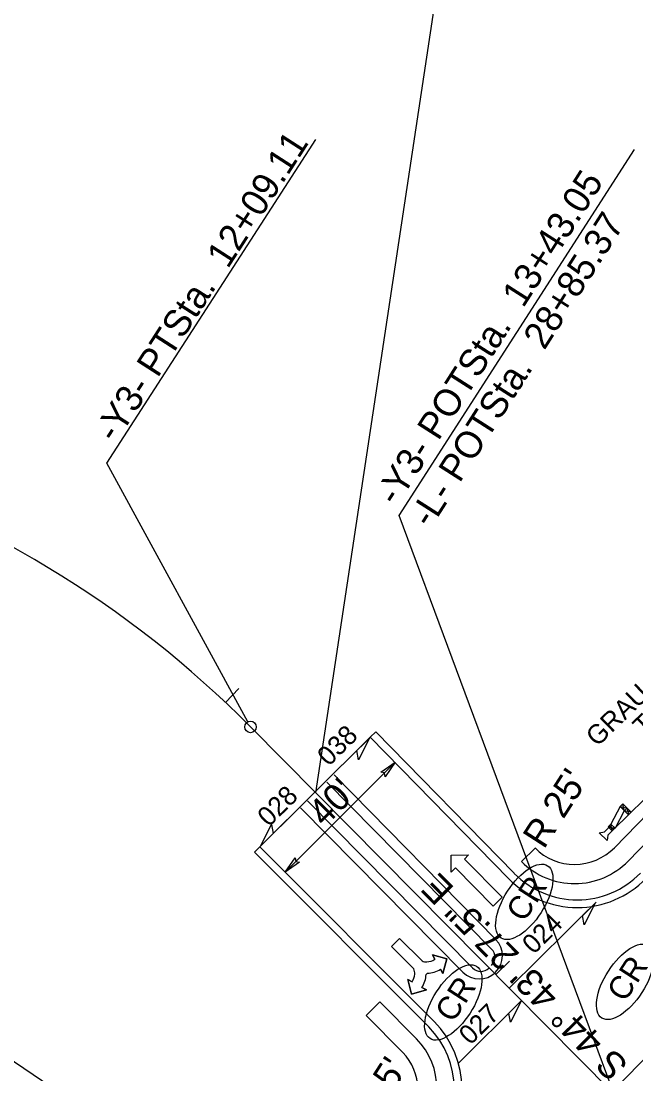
# Model space of a CAD drawing. Extents: x 1974386 to 1979988, y 776712 to 784860.
# Drawn here: x 1976659.3 to 1976819.6, y 779962.3 to 780236.8 of the extents above; entities that cross this region are included whole.
import ezdxf

# ---------------------------------------------------------------- set-up
doc = ezdxf.new("R2010")
doc.units = 0
for name, color, linetype in [('Prop Conc 2ft 6in Curb and Gutter', 7, 'Continuous'), ('Prop Conc 4in Sidewalk', 7, 'Continuous'), ('Prop Dimension', 7, 'Continuous'), ('Prop Dimension Text', 7, 'Continuous'), ('Prop EOT', 7, 'Continuous'), ('Prop Guardrail Anchor Unit CELL', 7, 'Continuous'), ('Prop Horizontal Alignment', 7, 'Continuous'), ('Prop Horizontal Alignment Direction Label', 7, 'Continuous'), ('Prop Horizontal Alignment Station Label', 7, 'Continuous'), ('Prop Horizontal Alignment Tick Small', 7, 'Continuous'), ('Prop Lane Arrow CELL', 7, 'Continuous'), ('Prop Superelevation  Arrow CELL', 7, 'Continuous'), ('Prop Superelevation Label', 7, 'Continuous'), ('Prop Terminator CELL', 7, 'Continuous'), ('Prop WCC CELL', 7, 'Continuous'), ('Sheet Layout Plan Border', 7, 'Continuous')]:
    doc.layers.add(name, color=color, linetype=linetype)

msp = doc.modelspace()

# ---------------------------------------------------------------- linework, layer by layer
at = {"layer": 'Prop Conc 2ft 6in Curb and Gutter'}
for p, q in [((1976751.75, 780051.46), (1976750.32, 780050.06)), ((1976751.75, 780051.46), (1976787.85, 780014.59)), ((1976738.98, 780038.4), (1976781.96, 779994.82)), ((1976733.99, 780033.46), (1976776.99, 779989.92)), ((1976720.09, 780020.1), (1976721.5, 780021.52)), ((1976720.09, 780020.1), (1976765.55, 779974.59))]:
    msp.add_line(p, q, dxfattribs=at)
for centre, radius, start, end in [((1976804.29, 780030.68), 23, 224.3953, 315.7395), ((1976779.82, 779992.71), 3, 314.6251, 44.6061), ((1976779.13, 779992.03), 3, 224.645, 314.6251), ((1976749.21, 779958.4), 23, 315.7395, 44.7138)]:
    msp.add_arc(centre, radius, start, end, dxfattribs=at)
at = {"layer": 'Prop Conc 4in Sidewalk'}
for p, q in [((1976813.97, 780021.28), (1976886.99, 780096.2)), ((1976890.27, 780092.42), (1976817.55, 780017.79)), ((1976789.73, 780017.67), (1976793.28, 780021.19)), ((1976752.79, 779981.08), (1976749.23, 779977.56)), ((1976752.79, 779981.08), (1976749.23, 779977.56)), ((1976752.79, 779981.08), (1976762.35, 779971.42)), ((1976762.35, 779971.42), (1976752.79, 779981.08)), ((1976749.23, 779977.56), (1976758.8, 779967.9)), ((1976749.23, 779977.56), (1976758.8, 779967.9))]:
    msp.add_line(p, q, dxfattribs=at)
for centre, radius, start, end in [((1976803.59, 780031.4), 14.5, 224.7243, 315.7395), ((1976803.59, 780031.4), 19.5, 224.7243, 315.7395), ((1976749.21, 779958.4), 18.5, 315.7395, 44.7243), ((1976749.21, 779958.4), 18.5, 315.7395, 44.7243), ((1976749.21, 779958.4), 13.5, 315.7395, 44.7243), ((1976749.21, 779958.4), 13.5, 315.7395, 44.7243)]:
    msp.add_arc(centre, radius, start, end, dxfattribs=at)
at = {"layer": 'Prop Dimension'}
msp.add_line((1976756.82, 780043.56), (1976728.12, 780014.89), dxfattribs=at)
at = {"layer": 'Prop EOT'}
for p, q in [((1976721.5, 780021.52), (1976750.32, 780050.06)), ((1976750.32, 780050.06), (1976786.42, 780013.19)), ((1976740.87, 780040.27), (1976783.06, 779997.3)), ((1976732.15, 780031.64), (1976774.46, 779988.83)), ((1976721.5, 780021.52), (1976766.97, 779976))]:
    msp.add_line(p, q, dxfattribs=at)
for centre, radius, start, end in [((1976804.29, 780030.68), 25, 224.3953, 315.7395), ((1976778.78, 779993.09), 6, 314.6608, 44.4765), ((1976778.73, 779993.04), 6, 224.6608, 314.6608), ((1976749.21, 779958.4), 25, 315.7395, 44.7243)]:
    msp.add_arc(centre, radius, start, end, dxfattribs=at)
at = {"layer": 'Prop Guardrail Anchor Unit CELL'}
for p, q in [((1976847.08, 780058.84), (1976813.79, 780026.01)), ((1976815.49, 780031.99), (1976813.09, 780027.43)), ((1976816.2, 780032.69), (1976815.49, 780031.99)), ((1976817.64, 780029.81), (1976815.49, 780031.99)), ((1976815.49, 780031.99), (1976817.27, 780031.6)), ((1976818.35, 780030.51), (1976816.2, 780032.69)), ((1976816.56, 780030.9), (1976816.2, 780032.69)), ((1976817.27, 780031.6), (1976816.56, 780030.9)), ((1976817.27, 780031.6), (1976817.64, 780029.81)), ((1976816.56, 780030.9), (1976814.15, 780026.37)), ((1976818.35, 780030.51), (1976816.56, 780030.9)), ((1976811.41, 780025.44), (1976812.84, 780026.9)), ((1976813.72, 780026.04), (1976812.28, 780024.58)), ((1976813.09, 780027.43), (1976812.38, 780026.73)), ((1976813.44, 780025.66), (1976812.38, 780026.73)), ((1976812.38, 780026.73), (1976814.15, 780026.37)), ((1976813.09, 780027.43), (1976812.74, 780027.08)), ((1976812.84, 780026.9), (1976813.28, 780026.47)), ((1976814.15, 780026.37), (1976813.09, 780027.43)), ((1976813.44, 780025.66), (1976813.09, 780027.43)), ((1976813.28, 780026.47), (1976813.72, 780026.04)), ((1976809.97, 780025.19), (1976811.41, 780025.44)), ((1976812.08, 780023.14), (1976809.97, 780025.19)), ((1976812.28, 780024.58), (1976812.08, 780023.14))]:
    msp.add_line(p, q, dxfattribs=at)
at = {"layer": 'Prop Horizontal Alignment'}
for p, q in [((1976566.21, 779704), (1976989.74, 780138.6)), ((1976719.09, 780052.76), (1976813.35, 779957.59)), ((1976719.09, 780052.76), (1976813.35, 779957.59))]:
    msp.add_line(p, q, dxfattribs=at)
msp.add_arc((1976525.24, 779860.76), 272.84, 44.7243, 72.9939, dxfattribs=at)
msp.add_arc((1976525.24, 779860.76), 272.84, 44.7243, 72.9939, dxfattribs=at)
at = {"layer": 'Prop Horizontal Alignment Station Label'}
for p, q in [((1976736.12, 780035.57), (1976772.23, 780274.59)), ((1976681.66, 780121.54), (1976736.1, 780205.88)), ((1976757.85, 780107.89), (1976819.23, 780203.33)), ((1976718.38, 780054.08), (1976681.66, 780121.54)), ((1976813.16, 779959.08), (1976757.85, 780107.89))]:
    msp.add_line(p, q, dxfattribs=at)
msp.add_circle((1976719.09, 780052.76), 1.5, dxfattribs=at)
at = {"layer": 'Prop Horizontal Alignment Tick Small'}
for p, q in [((1976712.58, 780059.12), (1976716.01, 780062.76)), ((1976783.05, 779988.18), (1976786.61, 779991.7))]:
    msp.add_line(p, q, dxfattribs=at)
at = {"layer": 'Prop Lane Arrow CELL'}
for p, q in [((1976771.43, 780019.35), (1976775.92, 780019.37)), ((1976771.45, 780014.93), (1976771.43, 780019.35)), ((1976775.92, 780019.37), (1976774.85, 780018.31)), ((1976774.85, 780018.31), (1976784.72, 780008.38)), ((1976772.51, 780015.99), (1976771.45, 780014.93)), ((1976782.37, 780006.05), (1976772.51, 780015.99)), ((1976784.72, 780008.38), (1976782.37, 780006.05)), ((1976755.83, 779995.51), (1976757.97, 779997.64)), ((1976757.97, 779997.64), (1976763.82, 779991.77)), ((1976761.64, 779989.67), (1976755.83, 779995.51)), ((1976767.13, 779992.17), (1976766.51, 779993.35)), ((1976766.51, 779993.35), (1976770.3, 779992.3)), ((1976770.3, 779992.3), (1976769.26, 779988.44)), ((1976764.87, 779988.21), (1976765.21, 779988.55)), ((1976769.26, 779988.44), (1976768.64, 779989.61)), ((1976761.08, 779983.12), (1976760.09, 779986.95)), ((1976760.09, 779986.95), (1976761.26, 779986.33)), ((1976764.98, 779984.18), (1976761.08, 779983.12)), ((1976763.81, 779984.8), (1976764.98, 779984.18))]:
    msp.add_line(p, q, dxfattribs=at)
for points in [[(1976763.83, 779991.76), (1976757.97, 779997.64), (1976755.83, 779995.51), (1976761.64, 779989.68)], [(1976768.64, 779989.61), (1976769.26, 779988.44), (1976770.3, 779992.3), (1976766.51, 779993.35), (1976767.14, 779992.18)], [(1976765.1, 779991.52), (1976765.1, 779991.52)], [(1976761.9, 779988.34), (1976761.9, 779988.34)], [(1976764.87, 779988.21), (1976765.21, 779988.55)], [(1976761.24, 779986.32), (1976760.09, 779986.95), (1976761.08, 779983.12), (1976764.98, 779984.18), (1976763.81, 779984.8)]]:
    msp.add_lwpolyline(points, dxfattribs=at)
for centre, radius, start, end in [((1976764.87, 779993.79), 2.28, 242.7954, 275.7934), ((1976764.87, 779993.79), 2.28, 242.7954, 275.7934), ((1976764.93, 779995.51), 4, 272.3033, 303.5159), ((1976764.93, 779995.51), 4, 272.3033, 303.5159), ((1976757.91, 779988.52), 4, 326.4996, 357.4297), ((1976757.91, 779988.52), 4, 326.4996, 357.4297), ((1976759.64, 779988.58), 2.28, 353.9396, 28.7057), ((1976759.64, 779988.58), 2.28, 353.9396, 28.7057), ((1976757.91, 779988.52), 6.97, 327.7395, 357.4349), ((1976757.91, 779988.52), 6.97, 327.7395, 357.4349), ((1976764.93, 779995.51), 6.97, 272.3033, 302.156), ((1976764.93, 779995.51), 6.97, 272.3033, 302.156)]:
    msp.add_arc(centre, radius, start, end, dxfattribs=at)
at = {"layer": 'Prop Superelevation  Arrow CELL'}
for p, q in [((1976740.66, 780040.49), (1976750.12, 780049.86)), ((1976721.7, 780021.71), (1976731.94, 780031.85)), ((1976809.2, 780007.03), (1976786.57, 779984.63)), ((1976773.3, 779965.09), (1976789.77, 779981.4))]:
    msp.add_line(p, q, dxfattribs=at)
for points in [[(1976750.12, 780049.86), (1976747.26, 780044.21), (1976746.83, 780046.6)], [(1976721.7, 780021.71), (1976724.55, 780027.35), (1976724.98, 780024.96)], [(1976808.99, 780006.83), (1976806.13, 780001.19), (1976805.7, 780003.57)], [(1976789.77, 779981.4), (1976786.91, 779975.76), (1976786.48, 779978.15)]]:
    msp.add_lwpolyline(points, close=True, dxfattribs=at)
at = {"layer": 'Prop Terminator CELL'}
for points in [[(1976753.09, 780040.93), (1976756.82, 780043.56), (1976754.19, 780039.79), (1976754.03, 780040.77)], [(1976731.85, 780017.52), (1976728.12, 780014.89), (1976730.76, 780018.65), (1976730.92, 780017.68)]]:
    msp.add_lwpolyline(points, close=True, dxfattribs=at)
at = {"layer": 'Prop WCC CELL'}
for centre in [(1976790.49, 780007.15), (1976816.78, 779986.3), (1976771.97, 779980.93)]:
    msp.add_ellipse(centre, major_axis=(6.07, 9.43), ratio=0.462467, dxfattribs=at)
at = {"layer": 'Sheet Layout Plan Border'}
msp.add_lwpolyline([(1976403.86, 778445.65), (1977189.89, 779604.17), (1976321, 780193.69), (1975534.97, 779035.17)], close=True, dxfattribs=at)

# ---------------------------------------------------------------- texts
at = {"layer": 'Prop Dimension Text'}
for s, rotation, p in [("R 25'", 57.255, (1976795.6, 780020.66)), ("40'", 44.97, (1976738.43, 780026.43)), ("R 25'", 57.255, (1976748.56, 779945.49))]:
    msp.add_text(s, height=7, rotation=rotation, dxfattribs=at).set_placement(p)
at = {"layer": 'Prop Guardrail Anchor Unit CELL'}
for s, p in [('GRAU 350', (1976809.52, 780047.39)), ('TL-3', (1976821.79, 780050.15))]:
    msp.add_text(s, height=5, rotation=44.1159, dxfattribs=at).set_placement(p)
at = {"layer": 'Prop Horizontal Alignment Direction Label'}
msp.add_text('S 44%%d 43\' 27.5" E', height=7, rotation=134.7243, dxfattribs=at).set_placement((1976817.94, 779964.81))
at = {"layer": 'Prop Horizontal Alignment Station Label'}
for s, rotation, p in [('-Y3- PTSta.  12+09.11', 57.255, (1976683.9, 780126.51)), ('-Y3- POTSta.  13+43.05', 57.448, (1976757.16, 780110.04)), ('-L- POTSta.  28+85.37', 57.448, (1976766.05, 780104.32))]:
    msp.add_text(s, height=7, rotation=rotation, dxfattribs=at).set_placement(p)
at = {"layer": 'Prop Superelevation Label'}
for s, p in [('038', (1976739.49, 780042.29)), ('028', (1976723.89, 780026.51)), ('024', (1976792.94, 779993.27)), ('027', (1976776.43, 779969.61))]:
    msp.add_text(s, height=5, rotation=44.7243, dxfattribs=at).set_placement(p)
at = {"layer": 'Prop WCC CELL'}
for p in [(1976790.43, 780001.58), (1976816.72, 779980.73), (1976771.9, 779975.37)]:
    msp.add_text('CR', height=6, rotation=57.255, dxfattribs=at).set_placement(p)

doc.saveas('drawing.dxf')
